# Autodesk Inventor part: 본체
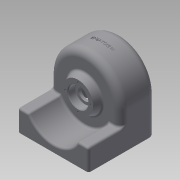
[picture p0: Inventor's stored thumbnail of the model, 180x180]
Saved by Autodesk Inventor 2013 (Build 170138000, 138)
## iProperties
Created: 2015-02
Part Number: 본체
Material: 일반
Document SubType Name: Modeling
Designer: Administrator
Density: 1 g/cm^3
Author: Administrator
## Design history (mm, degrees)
sketch "스케치1"
  geometry: L1 (0, 0)-(100, 0); L2 (100, 0)-(100, 95); L3 (100, 95)-(0, 95); L4 (0, 95)-(0, 0)
  constraints: 8 end point, 2 parallel, 1 horizontal, 1 perpendicular
  dimensions: "d0" = 100 distance of L1.start L1.end; "d1" = 95 distance of L3.end L1.start
extrude "돌출1" new body sketch "스케치1" distance "d2" = 30; taper "d3" = 0 deg
sketch "스케치2"
  geometry: L1 (0, 0)-(100, 0) reference; L2 (100, 0)-(100, 95) reference; L3 (100, 95)-(0, 95) reference; L4 (0, 95)-(0, 0) reference
node "작업 평면1"
sketch "스케치3"
  geometry: 1 further point
sketch "스케치4"
  geometry: L1 (100, 0)-(0, 0) reference; L2 (0, 0)-(0, 30) reference; L3 (100, 30)-(0, 30) reference; L4 (100, 0)-(100, 30) reference; C1 r 40 at (50, 50); 2 further points
  constraints: 1 centre point, 1 midpoint, 1 vertical alignment
  dimensions: "d5" = 80 diameter of C1; "d6" = 50 distance of point (50, 0) C1.centre
extrude "돌출2" cut sketch "스케치4" stored distance "d7" = 30; taper "d8" = 0 deg
sketch "스케치5"
  geometry: L1 (100, 0)-(0, 0) reference; L2 (0, 0)-(0, 30) reference; L3 (100, 30)-(0, 30) reference; L4 (100, 0)-(100, 30) reference; L5 (0, 50)-(0, 30); L6 (100, 50)-(100, 30); L7 (0, 30)-(100, 30); L8 (0, 30)-(100, 30); A1 r 50 centre (50, 50) between (0, 50) and (100, 50); 2 further points
  constraints: 8 end point, 2 collinear, 2 point on circle, 2 tangent, 1 centre point, 1 midpoint, 1 vertical alignment
  dimensions: "d9" = 100 diameter of A1; "d10" = 50 distance of point (50, 0) A1.centre
extrude "돌출3" join sketch "스케치5" stored distance "d11" = 30; taper "d12" = 0 deg
node "작업 평면2"
sketch "스케치6"
  geometry: L1 (100, 0)-(0, 0) reference; L2 (0, 0)-(0, 50) reference; L3 (100, 0)-(100, 50) reference; L4 (4, 50)-(4, 0); L5 (96, 50)-(96, 0); L6 (4, 0)-(96, 0); A1 r 50 centre (50, 50) between (100, 50) and (0, 50) reference; A2 r 46 centre (50, 50) between (4, 50) and (96, 50); 1 further point
  constraints: 6 end point, 2 perpendicular, 2 point on circle, 2 point on line, 2 tangent, 1 centre point, 1 coincident, 1 collinear
  dimensions: "d13" = 92 diameter of A2
extrude "돌출4" cut sketch "스케치6" stored distance "d14" = 42; taper "d15" = 0 deg
sketch "스케치7"
  geometry: C1 r 25 at (50, 50); A1 r 50 centre (50, 50) between (100, 50) and (0, 50) reference; 1 further point
  constraints: 1 centre point, 1 coincident
  dimensions: "d16" = 50 diameter of C1
extrude "돌출5" join sketch "스케치7" distance "d17" = 10; taper "d18" = 0 deg
sketch "스케치8"
  geometry: C1 r 20 at (50, -50); A1 r 50 centre (50, -50) between (0, -50) and (100, -50) reference
  constraints: 1 centre point, 1 coincident
  dimensions: "d19" = 40 diameter of C1
extrude "돌출6" join sketch "스케치8" distance "d20" = 9; taper "d21" = 0 deg
sketch "스케치9"
  geometry: C1 r 25 at (0, 0) reference; 1 further point
hole "구멍1" sketch "스케치9" at (0, 0) diameter "d22" = 20; stored, may be unused: countersink angle "d26" = 90 deg, drill point angle "d28" = 0 deg; dims "d23" = 6, "d24" = 28, "d25" = 10, "d27" = 8
sketch "스케치10"
  geometry: C1 r 20 at (0, 0) reference; 1 further point
sketch "스케치11"
  geometry: A1 r 46 centre (50, 50) between (96, 50) and (4, 50) reference; 1 further point
hole "구멍2" sketch "스케치11" at (50, 50) diameter "d29" = 20; stored, may be unused: countersink angle "d33" = 90 deg, drill point angle "d35" = 0 deg; dims "d30" = 6, "d31" = 28, "d32" = 8, "d34" = 2
sketch "스케치12"
  geometry: C1 r 14 at (0, 0) reference; C2 r 25 at (0, 0) reference; A1 r 18 centre (0, 0) between (0, 18) and (-18, 0); 3 further points
  constraints: 4 point on circle, 2 horizontal alignment, 1 centre point, 1 coincident, 1 vertical alignment
  dimensions: "d36" = 36 diameter of A1
hole "구멍3" sketch "스케치12" at (0, 18), (-18, 0), (0, -18), (18, 0) diameter "d37" = 2.459; stored, may be unused: countersink angle "d41" = 90 deg, drill point angle "d43" = 0 deg; dims "d38" = 6, "d39" = 28, "d40" = 8, "d42" = 9
sketch "스케치13"
  geometry: L1 (-4, 49)-(-96, 49) reference; L2 (0, 0)-(-100, 0) reference; L3 (-100, 0)-(-100, 95) reference; L4 (-91.75, 9)-(-8.25, 9); 4 further points
  constraints: 3 vertical alignment, 2 end point, 2 horizontal alignment, 2 midpoint, 1 perpendicular
  dimensions: "d44" = 9 distance from line of L4.start L2; "d45" = 83.5 distance of L4.end L4.start; "d46" = 33 distance of L4.start point (-91.75, 42)
hole "구멍4" sketch "스케치13" at (-91.75, 42), (-91.75, 9), (-8.25, 9), (-8.25, 42) diameter "d47" = 5.134; stored, may be unused: countersink angle "d51" = 90 deg, drill point angle "d53" = 0 deg; dims "d48" = 10, "d49" = 28, "d50" = 8, "d52" = 13
node "작업 평면3"
sketch "스케치14"
  geometry: L1 (50, 50)-(-50, 50) reference; L2 (-50, 0)-(-50, 50) reference; L3 (50, 0)-(-50, 0) reference; L4 (50, 0)-(50, 50) reference; 3 further points
  constraints: 1 midpoint, 1 vertical alignment, 1 other
  dimensions: "d54" = 25 distance of point (0, 25) point (0, 50)
feature "엠보싱1" sketch "스케치14" dims "d55" = 0.5, "d56" = 0
fillet "모깎기1" dims "d57" = 10
fillet "모깎기2" dims "d58" = 6
fillet "모깎기3" dims "d59" = 3
fillet "모깎기4" dims "d60" = 3
fillet "모깎기5" dims "d61" = 3
fillet "모깎기6" dims "d62" = 3
feature "면 기울기1" dims angle "d63" = 20 deg
fillet "모깎기7" dims "d64" = 3
fillet "모깎기8" dims "d65" = 3
fillet "모깎기9" dims "d66" = 3
fillet "모깎기10" dims "d67" = 0.3
fillet "모깎기11" dims "d68" = 0.3
fillet "모깎기12" dims "d69" = 3
chamfer "모따기1" distance "d70" = 1; stored, may be unused: second distance "d71" = 2, angle "d72" = 45 deg
chamfer "모따기2" distance "d73" = 1; stored, may be unused: second distance "d74" = 2, angle "d75" = 45 deg
node "솔리드1"
node "투영된 루프1"
node "투영된 루프2"
node "투영된 루프3"
node "투영된 루프4"
